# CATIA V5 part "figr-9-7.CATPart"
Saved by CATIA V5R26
Part number: Part2
Bounding box of the stored display mesh (mm): x -96.278 to 96.278, y -96.278 to 96.278, z -26.878 to 0
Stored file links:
  D:\_Deepak\CATIA\CATIA V5-6R2016_Deepak\Resources\Part files\Partfiles\c09_catia_v5_6r2016_prt\figr-9-7.CATPart
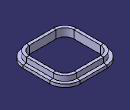
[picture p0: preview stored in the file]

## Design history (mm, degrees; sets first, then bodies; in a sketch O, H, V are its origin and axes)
Body1 (main body)
  Sketch1 on xy-plane, origin (0, 0, 0), H (1, 0, 0), V (0, 1, 0)
    point P1 (-75, 75)
    line L1 (-45, 75) -> (45, 75)
    line L2 (75, 45) -> (75, -45)
    line L3 (45, -75) -> (-45, -75)
    line L4 (-75, -45) -> (-75, 45)
    point P2 (75, 75)
    point P3 (75, -75)
    point P4 (-75, -75)
    axis line L5 (75, -75) -> (-75, 75)
    arc A1 centre (45, -45) radius 30 from (75, -45) to (45, -75) cw
    arc A2 centre (45, 45) radius 30 from (45, 75) to (75, 45) cw
    arc A3 centre (-45, 45) radius 30 from (-45, 75) to (-75, 45) ccw
    arc A4 centre (-45, -45) radius 30 from (-45, -75) to (-75, -45) cw
    distance P2 P3 = 150
    distance P3 P4 = 150
    radius A1 = 30
    radius A2 = 30
    radius A3 = 30
    radius A4 = 30
    horizontal: L1 H, L3 H
    vertical: L2 V, L4 V
    midpoint: O L5
    coincidence: L2 P3, L3 P3, L1 P2, L2 P2, L1 P1, L4 P1, L3 P4, L4 P4
    tangency: A1 L2, A1 L3, A2 L1, A2 L2, A3 L1, A3 L4, A4 L3, A4 L4
  Sketch2 on yz-plane, origin (0, 0, 0), H (0, 1, 0), V (0, 0, 1)
    point P1 (85, 0)
    line L1 (85, 0) -> (85, -16.8782)
    line L2 (85, -16.8782) -> (96.2781, -16.8782)
    line L3 (96.2781, -16.8782) -> (96.2781, -26.8782)
    line L4 (96.2781, -26.8782) -> (75, -26.8782)
    line L5 (75, -26.8782) -> (75, 0)
    point P6 (75, 0)
    line L6 (75, 0) -> (85, 0)
    reference projected point E1 (75, 0) from edge of Sketch1
    length L3 = 10
    length L6 = 10
    coincidence: P1 H, P6 H, P6 E1
    vertical: L1 V, L3 V, L5 V
    horizontal: L2 H, L4 H, L6 H
  Rib1: profile Sketch2, centre curve Sketch1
